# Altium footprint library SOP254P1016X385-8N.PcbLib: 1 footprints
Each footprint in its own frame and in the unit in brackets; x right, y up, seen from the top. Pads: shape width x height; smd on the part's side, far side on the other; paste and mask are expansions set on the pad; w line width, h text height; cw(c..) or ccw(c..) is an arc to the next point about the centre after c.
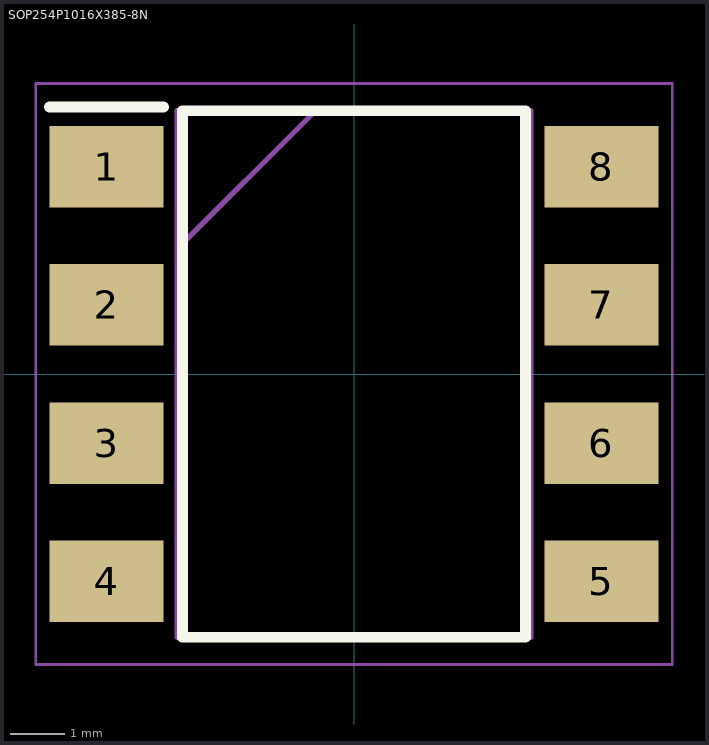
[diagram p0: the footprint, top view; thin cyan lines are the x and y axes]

## SOP254P1016X385-8N [mm]
pads (8):
  rect 2.1x1.5 smd: 1(-4.55,3.81) 2(-4.55,1.27) 3(-4.55,-1.27) 4(-4.55,-3.81) 5(4.55,-3.81) 6(4.55,-1.27) 7(4.55,1.27) 8(4.55,3.81)
Top Overlay:
  lines w0.2: -5.6,4.91 -3.5,4.91 ; -3.15,-4.84 3.15,-4.84 3.15,4.84 -3.15,4.84 -3.15,-4.84
Mechanical 15:
  lines w0.1: -3.25,2.3 -0.71,4.84 ; -3.25,-4.84 3.25,-4.84 3.25,4.84 -3.25,4.84 -3.25,-4.84
Mechanical 20:
  lines w0.05: -5.85,-5.34 5.85,-5.34 5.85,5.34 -5.85,5.34 -5.85,-5.34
